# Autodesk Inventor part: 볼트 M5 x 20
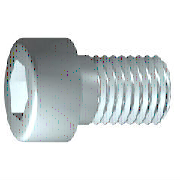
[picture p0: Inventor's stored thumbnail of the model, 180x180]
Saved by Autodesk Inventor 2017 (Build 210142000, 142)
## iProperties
Created: 2012-02
Part Number: 볼트 M5 x 20
Material: 스테인리스강
Description: 6각 소켓 머리 캡 나사
Document SubType Name: Modeling
Standard: ISO 4762
Designer: mduedu
Standard Revision: Fourth edition 2004-03-01
Standards Organization: ISO
Language: ko-KR
Size Designation: M5 x 20
Categories: <MemberInstance><Categories><Category DisplayName="조임쇠" InternalName="e4da775c-781d-43d5-af7c-5136215cf5a6" Mnemonic="FSTN"><Category DisplayName="볼트" InternalN
Density: 8.08 g/cm^3
Mass: 5.10181 g
Surface Area: 5.88237 cm^2
Volume: 0.631412 cm^3
Appearance: 반광택
IsCustomPart: 0
Author: mduedu
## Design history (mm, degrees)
sketch "스케치1"
  geometry: L1 (-1.167, 0)-(20, 0); L2 (20, 0)-(20, 2.5); L3 (20, 2.5)-(2, 2.5); L4 (2, 2.5)-(1.509, 2.5); L5 (1.509, 2.5)-(0, 2.5); L6 (0, 2.5)-(0, 4.25); L7 (0, 4.25)-(-5, 4.25); L8 (-5, 4.25)-(-5, 2.309); L9 (-5, 2.309)-(-2.5, 2.309); L10 (-2.5, 2.309)-(-1.167, 0); L11 (-10, 0)-(25, 0) reference; L12 (0, -0.85)-(0, 5.1) reference; L13 (2, 2.5)-(0, 2.5)
  constraints: 22 end point, 6 parallel, 2 collinear, 2 perpendicular, 1 horizontal, 1 point on line
  dimensions: "d1" = 18 distance from line of L3.end L2 (= GEL); "d2" = 0.49086 distance of L4.end L3.end (computed from GAL); "d3" = 5 distance between parallel lines of L8 L6 (= KOH); "d4" = 2.5 distance of L8.end L9.end (= INTI); "d5" = 60 deg angle of L10 L1; "d6" = 5 diameter of L3 L1 (= GD); "d7" = 5 diameter of L5 L1 (= BDM); "d8" = 4.6188 diameter of L9 L1 (= 1.1547 x SW); "d9" = 8.5 diameter of L7 L1 (= KOD); "d26" = 20 distance between parallel lines of L12 L2 (= NLG)
revolve "본체" sketch "스케치1" stored, may be unused: angle "d10" = 90 deg
sketch "스케치2"
  geometry: L1 (0, -5.95)-(0, 5.95) reference; L2 (-5.95, 0)-(5.95, 0) reference; L3 (2.309, 0)-(1.155, -2); L4 (1.155, -2)-(-1.155, -2); L5 (-1.155, -2)-(-2.309, 0); L6 (-2.309, 0)-(-1.155, 2); L7 (-1.155, 2)-(1.155, 2); L8 (1.155, 2)-(2.309, 0); 2 further points
  constraints: 12 end point, 1 coincident, 1 horizontal alignment, 1 point on line, 12 other
extrude "슬롯" join sketch "스케치2" stored distance "d11" = 10; taper "d12" = 0 deg
workplane "Work Plane1"
fillet "Fillet2" dims "d30" = 0.1 (= R)
body "Solid1"
fillet "모깎기1" dims "d17" = 0.5 (= RR)
feature "스레드" dims "d13" = 18 (= GEL), "d14" = 0
chamfer "모따기1" distance "d15" = 0.49076 (= -0.5 x SPD + 0.5 x GD); stored, may be unused: second distance "d16" = 0.49076 (= GUL), angle "d27" = 45 deg
other parameters: "GD" = 5 [user parameter; used in 2 equation terms], "NLG" = 20 [user parameter; used in 1 equation term], "GEL" = 18 [user parameter; used in 2 equation terms], "KOD" = 8.5 [user parameter; used in 1 equation term], "KOH" = 5 [user parameter; used in 1 equation term], "INTI" = 2.5 [user parameter; used in 1 equation term], "GAL" = 0.49076 (= 0.61345 x PTC) [user parameter; used in 1 equation term], "GUL" = 0.49076 (= 0.61345 x PTC) [user parameter; used in 1 equation term], "BDM" = 5 (= NND) [user parameter; used in 1 equation term], "SW" = 4 [user parameter; used in 2 equation terms], "RR" = 0.5 [user parameter; used in 1 equation term], "SPD" = 4.01848 (= NND - 1.2269 x PTC) [user parameter; used in 1 equation term], "d19" = 0, "d28" = 0, "d29" = 0, "R" = 0.1 [user parameter; used in 1 equation term], "TOA" = 30 deg [user parameter], "GD1" = 4.01848 (= THREADDIA - 1.2269 x PTC) [user parameter], "THREADDIA" = 5 [user parameter; used in 1 equation term], "FAWI" = 45 deg [user parameter], "TPU" = 12.5 (computed from PTC) [user parameter], "PTC" = 0.8 [user parameter; used in 5 equation terms], "NND" = 5 [user parameter; used in 2 equation terms], "E0" = 4.62 (= 1.155 x SW) [user parameter]
